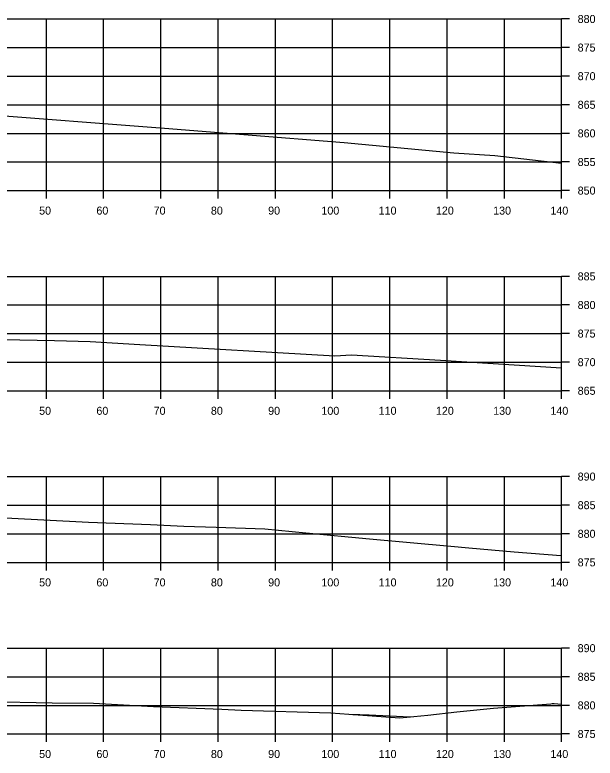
# Model space of a CAD drawing. Extents: x 1098669 to 1198896, y 698679 to 704410.
# Drawn here: x 1110825.7 to 1110927, y 701654.9 to 701784.8 of the extents above; entities that cross this region are included whole.
import ezdxf

# ---------------------------------------------------------------- set-up
doc = ezdxf.new("R2010")
doc.units = 0
for name, color, linetype in [('Proposed Surface', 7, 'Continuous'), ('R_Axis', 7, 'Continuous'), ('R_Axis Annot', 7, 'Continuous'), ('R_Fin Surface', 7, 'Continuous'), ('R_Grid', 7, 'Continuous')]:
    doc.layers.add(name, color=color, linetype=linetype)

msp = doc.modelspace()

# ---------------------------------------------------------------- linework, layer by layer
at = {"layer": 'Proposed Surface'}
for points in [[(1110818.51, 701767.61), (1110851.8, 701765.03), (1110865.64, 701763.92), (1110883.18, 701762.52), (1110902.35, 701760.74), (1110909.51, 701760.29), (1110921.16, 701758.94)], [(1110814.33, 701728.24), (1110832.59, 701727.9), (1110838.82, 701727.76), (1110847.49, 701727.2), (1110881.52, 701725.26), (1110884.48, 701725.43), (1110900.02, 701724.48), (1110921.16, 701723.13)], [(1110824.05, 701696.94), (1110838.5, 701696.15), (1110849.36, 701695.73), (1110855.17, 701695.46), (1110860.81, 701695.3), (1110869.35, 701694.98), (1110876.49, 701694.32), (1110887.61, 701693.23), (1110901.81, 701691.97), (1110904.93, 701691.68), (1110912.88, 701690.99), (1110921, 701690.34), (1110921.16, 701690.33)], [(1110820.88, 701664.81), (1110832.15, 701664.6), (1110839.37, 701664.49), (1110849.85, 701663.94), (1110861.81, 701663.47), (1110865.16, 701663.27), (1110880.87, 701662.83), (1110884.02, 701662.61), (1110892.89, 701661.98), (1110897.81, 701662.41), (1110902.83, 701663.02), (1110909.26, 701663.67), (1110919.28, 701664.42), (1110919.49, 701664.43), (1110919.84, 701664.46), (1110921.16, 701664.35)]]:
    msp.add_lwpolyline(points, dxfattribs=at)
at = {"layer": 'R_Axis'}
for p, q in [((1110921.16, 701754.13), (1110921.16, 701784.13)), ((1110922.56, 701784.13), (1110921.16, 701784.13)), ((1110922.56, 701779.13), (1110921.16, 701779.13)), ((1110922.56, 701774.13), (1110921.16, 701774.13)), ((1110922.56, 701769.13), (1110921.16, 701769.13)), ((1110922.56, 701764.13), (1110921.16, 701764.13)), ((1110922.56, 701759.13), (1110921.16, 701759.13)), ((1110641.16, 701754.13), (1110921.16, 701754.13)), ((1110831.16, 701752.73), (1110831.16, 701754.13)), ((1110841.16, 701752.73), (1110841.16, 701754.13)), ((1110851.16, 701752.73), (1110851.16, 701754.13)), ((1110861.16, 701752.73), (1110861.16, 701754.13)), ((1110871.16, 701752.73), (1110871.16, 701754.13)), ((1110881.16, 701752.73), (1110881.16, 701754.13)), ((1110891.16, 701752.73), (1110891.16, 701754.13)), ((1110901.16, 701752.73), (1110901.16, 701754.13)), ((1110911.16, 701752.73), (1110911.16, 701754.13)), ((1110921.16, 701752.73), (1110921.16, 701754.13)), ((1110922.56, 701754.13), (1110921.16, 701754.13)), ((1110921.16, 701719.13), (1110921.16, 701739.13)), ((1110922.56, 701739.13), (1110921.16, 701739.13)), ((1110922.56, 701734.13), (1110921.16, 701734.13)), ((1110922.56, 701729.13), (1110921.16, 701729.13)), ((1110922.56, 701724.13), (1110921.16, 701724.13)), ((1110641.16, 701719.13), (1110921.16, 701719.13)), ((1110831.16, 701717.73), (1110831.16, 701719.13)), ((1110841.16, 701717.73), (1110841.16, 701719.13)), ((1110851.16, 701717.73), (1110851.16, 701719.13)), ((1110861.16, 701717.73), (1110861.16, 701719.13)), ((1110871.16, 701717.73), (1110871.16, 701719.13)), ((1110881.16, 701717.73), (1110881.16, 701719.13)), ((1110891.16, 701717.73), (1110891.16, 701719.13)), ((1110901.16, 701717.73), (1110901.16, 701719.13)), ((1110911.16, 701717.73), (1110911.16, 701719.13)), ((1110921.16, 701717.73), (1110921.16, 701719.13)), ((1110922.56, 701719.13), (1110921.16, 701719.13)), ((1110921.16, 701689.13), (1110921.16, 701704.13)), ((1110922.56, 701704.13), (1110921.16, 701704.13)), ((1110922.56, 701699.13), (1110921.16, 701699.13)), ((1110922.56, 701694.13), (1110921.16, 701694.13)), ((1110641.16, 701689.13), (1110921.16, 701689.13)), ((1110831.16, 701687.73), (1110831.16, 701689.13)), ((1110841.16, 701687.73), (1110841.16, 701689.13)), ((1110851.16, 701687.73), (1110851.16, 701689.13)), ((1110861.16, 701687.73), (1110861.16, 701689.13)), ((1110871.16, 701687.73), (1110871.16, 701689.13)), ((1110881.16, 701687.73), (1110881.16, 701689.13)), ((1110891.16, 701687.73), (1110891.16, 701689.13)), ((1110901.16, 701687.73), (1110901.16, 701689.13)), ((1110911.16, 701687.73), (1110911.16, 701689.13)), ((1110921.16, 701687.73), (1110921.16, 701689.13)), ((1110922.56, 701689.13), (1110921.16, 701689.13)), ((1110921.16, 701659.13), (1110921.16, 701674.13)), ((1110922.56, 701674.13), (1110921.16, 701674.13)), ((1110922.56, 701669.13), (1110921.16, 701669.13)), ((1110922.56, 701664.13), (1110921.16, 701664.13)), ((1110641.16, 701659.13), (1110921.16, 701659.13)), ((1110831.16, 701657.73), (1110831.16, 701659.13)), ((1110841.16, 701657.73), (1110841.16, 701659.13)), ((1110851.16, 701657.73), (1110851.16, 701659.13)), ((1110861.16, 701657.73), (1110861.16, 701659.13)), ((1110871.16, 701657.73), (1110871.16, 701659.13)), ((1110881.16, 701657.73), (1110881.16, 701659.13)), ((1110891.16, 701657.73), (1110891.16, 701659.13)), ((1110901.16, 701657.73), (1110901.16, 701659.13)), ((1110911.16, 701657.73), (1110911.16, 701659.13)), ((1110921.16, 701657.73), (1110921.16, 701659.13)), ((1110922.56, 701659.13), (1110921.16, 701659.13))]:
    msp.add_line(p, q, dxfattribs=at)
at = {"layer": 'R_Fin Surface'}
msp.add_lwpolyline([(1110884.7, 701662.56), (1110885.89, 701662.52), (1110885.89, 701662.52), (1110887.53, 701662.45), (1110887.55, 701662.45), (1110893.5, 701662.19), (1110894.74, 701662.14)], dxfattribs=at)
at = {"layer": 'R_Grid'}
for p, q in [((1110641.16, 701784.13), (1110921.16, 701784.13)), ((1110831.16, 701754.13), (1110831.16, 701784.13)), ((1110841.16, 701754.13), (1110841.16, 701784.13)), ((1110851.16, 701754.13), (1110851.16, 701784.13)), ((1110861.16, 701754.13), (1110861.16, 701784.13)), ((1110871.16, 701754.13), (1110871.16, 701784.13)), ((1110881.16, 701754.13), (1110881.16, 701784.13)), ((1110891.16, 701754.13), (1110891.16, 701784.13)), ((1110901.16, 701754.13), (1110901.16, 701784.13)), ((1110911.16, 701754.13), (1110911.16, 701784.13)), ((1110921.16, 701754.13), (1110921.16, 701784.13)), ((1110641.16, 701779.13), (1110921.16, 701779.13)), ((1110641.16, 701774.13), (1110921.16, 701774.13)), ((1110641.16, 701769.13), (1110921.16, 701769.13)), ((1110641.16, 701764.13), (1110921.16, 701764.13)), ((1110641.16, 701759.13), (1110921.16, 701759.13)), ((1110641.16, 701754.13), (1110921.16, 701754.13)), ((1110641.16, 701739.13), (1110921.16, 701739.13)), ((1110831.16, 701719.13), (1110831.16, 701739.13)), ((1110841.16, 701719.13), (1110841.16, 701739.13)), ((1110851.16, 701719.13), (1110851.16, 701739.13)), ((1110861.16, 701719.13), (1110861.16, 701739.13)), ((1110871.16, 701719.13), (1110871.16, 701739.13)), ((1110881.16, 701719.13), (1110881.16, 701739.13)), ((1110891.16, 701719.13), (1110891.16, 701739.13)), ((1110901.16, 701719.13), (1110901.16, 701739.13)), ((1110911.16, 701719.13), (1110911.16, 701739.13)), ((1110921.16, 701719.13), (1110921.16, 701739.13)), ((1110641.16, 701734.13), (1110921.16, 701734.13)), ((1110641.16, 701729.13), (1110921.16, 701729.13)), ((1110641.16, 701724.13), (1110921.16, 701724.13)), ((1110641.16, 701719.13), (1110921.16, 701719.13)), ((1110641.16, 701704.13), (1110921.16, 701704.13)), ((1110831.16, 701689.13), (1110831.16, 701704.13)), ((1110841.16, 701689.13), (1110841.16, 701704.13)), ((1110851.16, 701689.13), (1110851.16, 701704.13)), ((1110861.16, 701689.13), (1110861.16, 701704.13)), ((1110871.16, 701689.13), (1110871.16, 701704.13)), ((1110881.16, 701689.13), (1110881.16, 701704.13)), ((1110891.16, 701689.13), (1110891.16, 701704.13)), ((1110901.16, 701689.13), (1110901.16, 701704.13)), ((1110911.16, 701689.13), (1110911.16, 701704.13)), ((1110921.16, 701689.13), (1110921.16, 701704.13)), ((1110641.16, 701699.13), (1110921.16, 701699.13)), ((1110641.16, 701694.13), (1110921.16, 701694.13)), ((1110641.16, 701689.13), (1110921.16, 701689.13)), ((1110641.16, 701674.13), (1110921.16, 701674.13)), ((1110831.16, 701659.13), (1110831.16, 701674.13)), ((1110841.16, 701659.13), (1110841.16, 701674.13)), ((1110851.16, 701659.13), (1110851.16, 701674.13)), ((1110861.16, 701659.13), (1110861.16, 701674.13)), ((1110871.16, 701659.13), (1110871.16, 701674.13)), ((1110881.16, 701659.13), (1110881.16, 701674.13)), ((1110891.16, 701659.13), (1110891.16, 701674.13)), ((1110901.16, 701659.13), (1110901.16, 701674.13)), ((1110911.16, 701659.13), (1110911.16, 701674.13)), ((1110921.16, 701659.13), (1110921.16, 701674.13)), ((1110641.16, 701669.13), (1110921.16, 701669.13)), ((1110641.16, 701664.13), (1110921.16, 701664.13)), ((1110641.16, 701659.13), (1110921.16, 701659.13))]:
    msp.add_line(p, q, dxfattribs=at)

# ---------------------------------------------------------------- texts
at = {"layer": 'R_Axis Annot'}
for s, p in [('880', (1110923.96, 701783.43)), ('875', (1110923.96, 701778.43)), ('870', (1110923.96, 701773.43)), ('865', (1110923.96, 701768.43)), ('860', (1110923.96, 701763.43)), ('855', (1110923.96, 701758.43)), ('850', (1110923.96, 701753.43)), ('50', (1110829.9, 701749.93)), ('60', (1110839.9, 701749.93)), ('70', (1110849.9, 701749.93)), ('80', (1110859.9, 701749.93)), ('90', (1110869.9, 701749.93)), ('100', (1110879.2, 701749.93)), ('110', (1110889.2, 701749.93)), ('120', (1110899.2, 701749.93)), ('130', (1110909.2, 701749.93)), ('140', (1110919.2, 701749.93)), ('885', (1110923.96, 701738.43)), ('880', (1110923.96, 701733.43)), ('875', (1110923.96, 701728.43)), ('870', (1110923.96, 701723.43)), ('865', (1110923.96, 701718.43)), ('50', (1110829.9, 701714.93)), ('60', (1110839.9, 701714.93)), ('70', (1110849.9, 701714.93)), ('80', (1110859.9, 701714.93)), ('90', (1110869.9, 701714.93)), ('100', (1110879.2, 701714.93)), ('110', (1110889.2, 701714.93)), ('120', (1110899.2, 701714.93)), ('130', (1110909.2, 701714.93)), ('140', (1110919.2, 701714.93)), ('890', (1110923.96, 701703.43)), ('885', (1110923.96, 701698.43)), ('880', (1110923.96, 701693.43)), ('875', (1110923.96, 701688.43)), ('50', (1110829.9, 701684.93)), ('60', (1110839.9, 701684.93)), ('70', (1110849.9, 701684.93)), ('80', (1110859.9, 701684.93)), ('90', (1110869.9, 701684.93)), ('100', (1110879.2, 701684.93)), ('110', (1110889.2, 701684.93)), ('120', (1110899.2, 701684.93)), ('130', (1110909.2, 701684.93)), ('140', (1110919.2, 701684.93)), ('890', (1110923.96, 701673.43)), ('885', (1110923.96, 701668.43)), ('880', (1110923.96, 701663.43)), ('875', (1110923.96, 701658.43)), ('50', (1110829.9, 701654.93)), ('60', (1110839.9, 701654.93)), ('70', (1110849.9, 701654.93)), ('80', (1110859.9, 701654.93)), ('90', (1110869.9, 701654.93)), ('100', (1110879.2, 701654.93)), ('110', (1110889.2, 701654.93)), ('120', (1110899.2, 701654.93)), ('130', (1110909.2, 701654.93)), ('140', (1110919.2, 701654.93))]:
    msp.add_text(s, height=1.4, dxfattribs=at).set_placement(p)

doc.saveas('drawing.dxf')
